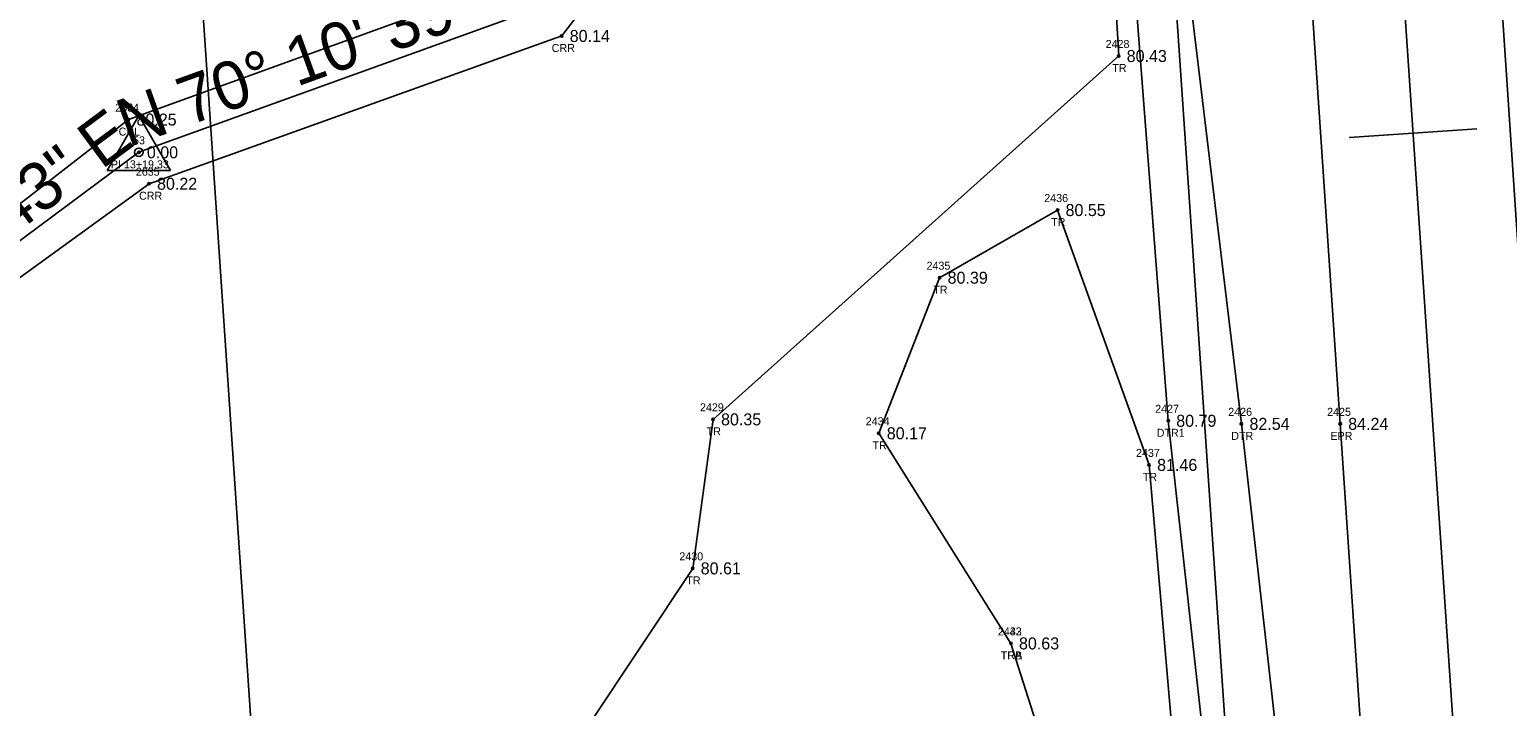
# Model space of a CAD drawing. Extents: x 2139392 to 2143384, y 505395 to 510520.
# Drawn here: x 2140461 to 2140645.6, y 506654.9 to 506739.4 of the extents above; entities that cross this region are included whole.
import ezdxf

# ---------------------------------------------------------------- set-up
doc = ezdxf.new("R2010")
doc.units = 0
for name, color, linetype in [('RD_EV_EX_Wetlands', 7, 'Continuous'), ('RD_EX_H2O', 7, 'Continuous'), ('RD_EX_H2O_txCode', 7, 'Continuous'), ('RD_EX_Road', 7, 'Continuous'), ('RD_EX_Road_txCode', 7, 'Continuous'), ('RD_EX_TX_H2O_ELEV', 7, 'Continuous'), ('RD_EX_TX_Road_ELEV', 7, 'Continuous'), ('RD_EX_TX_VEG_ELEV', 7, 'Continuous'), ('RD_EX_VEG', 7, 'Continuous'), ('RD_EX_VEG_txCode', 7, 'Continuous'), ('RD_HC_Cl', 7, 'Continuous'), ('RD_HC_Data', 7, 'Continuous'), ('RD_HC_Data_Tic', 7, 'Continuous'), ('RD_HC_Survey_ELEV', 7, 'Continuous'), ('RD_HC_txCode', 7, 'Continuous'), ('RD_SMD_Locator', 7, 'Continuous')]:
    doc.layers.add(name, color=color, linetype=linetype)

msp = doc.modelspace()

# ---------------------------------------------------------------- linework, layer by layer
at = {"layer": 'RD_EV_EX_Wetlands'}
msp.add_line((2140635.69, 506280.8), (2140603.94, 506746.81), dxfattribs=at)
msp.add_lwpolyline([(2140635.69, 506280.8), (2140514.52, 506270.54), (2140464.28, 507012.49), (2140535.71, 507012.16)], dxfattribs=at)
at = {"layer": 'RD_EX_H2O'}
for points in [[(2140595.86, 506808.79), (2140590.86, 506807.57), (2140591.7, 506801.01), (2140576.01, 506792.99), (2140551.31, 506782.03), (2140521.97, 506745.85), (2140473.31, 506728.17), (2140432.02, 506696.18), (2140374.62, 506691.81), (2140362.76, 506675.27), (2140331.34, 506688.09), (2140289.89, 506693.34), (2140243.27, 506706.89), (2140157.85, 506698.32), (2140125.33, 506735.71)], [(2140599.39, 506797.89), (2140612.39, 506690.17), (2140624.13, 506585.64), (2140631.8, 506471.85), (2140639.71, 506372.71), (2140644.64, 506264.35)], [(2140597.11, 506796.14), (2140592.29, 506797.04), (2140578.11, 506789.28), (2140556.31, 506776.27), (2140527.45, 506738.61), (2140475.88, 506720.16), (2140433.27, 506689.29), (2140378.98, 506685.41), (2140363.61, 506658.12), (2140329.18, 506677.67), (2140287.66, 506681.81), (2140243.93, 506698.42), (2140156.17, 506695.49), (2140124.7, 506729.24)], [(2140592.29, 506797.04), (2140595.23, 506794.56), (2140603.24, 506690.55), (2140614.93, 506584.96), (2140623.5, 506470.62), (2140631.3, 506372.18), (2140637.44, 506263.69)]]:
    msp.add_lwpolyline(points, dxfattribs=at)
at = {"layer": 'RD_EX_Road'}
for points in [[(2140559.74, 507699.59), (2140559.81, 507681.93), (2140560.3, 507666.18), (2140562.28, 507610.8), (2140566.4, 507547.54), (2140570.03, 507492.8), (2140573.82, 507437.38), (2140577.82, 507379.04), (2140579.38, 507354.44), (2140581.03, 507330.09), (2140587.99, 507226.36), (2140590.86, 507184.68), (2140593.07, 507153.16), (2140595.23, 507123.79), (2140602.7, 507012.79), (2140610.01, 506906.42), (2140617.09, 506803.24), (2140624.73, 506690.17), (2140631.76, 506586.09), (2140639.51, 506472.79), (2140646.1, 506374.38), (2140653.64, 506264.11)], [(2140620.89, 507096.21), (2140626.38, 507013.96), (2140633.64, 506909.47), (2140640.76, 506804.87), (2140648.25, 506692.59), (2140655.54, 506588.36), (2140663.28, 506474.49), (2140669.92, 506375.75), (2140677.52, 506265.2)]]:
    msp.add_lwpolyline(points, dxfattribs=at)
at = {"layer": 'RD_EX_VEG'}
for points in [[(2140538.67, 507155.75), (2140561.07, 507147.8), (2140571.22, 507149.28), (2140587.08, 506901.77), (2140597.05, 506736.11), (2140546.36, 506690.73), (2140543.82, 506672.12), (2140517.74, 506632.93), (2140477.73, 506581.98)], [(2140583.59, 506662.75), (2140567.07, 506688.99), (2140574.67, 506708.42), (2140589.41, 506716.87), (2140600.85, 506685.04), (2140609.88, 506580.26), (2140583.59, 506662.75)]]:
    msp.add_lwpolyline(points, dxfattribs=at)
at = {"layer": 'RD_HC_Cl'}
for p, q in [((2140574.74, 507595.12), (2140664.08, 506281.81)), ((2140474.61, 506724.08), (2140525.23, 506742.33)), ((2140432.56, 506692.9), (2140474.61, 506724.08))]:
    msp.add_line(p, q, dxfattribs=at)
at = {"layer": 'RD_HC_Data'}
for p, q in [((2140470.64, 506721.79), (2140474.61, 506728.67)), ((2140474.61, 506728.67), (2140478.58, 506721.79)), ((2140470.64, 506721.79), (2140478.58, 506721.79))]:
    msp.add_line(p, q, dxfattribs=at)
msp.add_circle((2140474.61, 506724.08), 0.529, dxfattribs=at)
at = {"layer": 'RD_HC_Data_Tic'}
for q in [(2140641.81, 506727), (2140625.85, 506725.92)]:
    msp.add_line((2140633.83, 506726.46), q, dxfattribs=at)
at = {"layer": 'RD_SMD_Locator'}
for centre in [(2140527.45, 506738.61), (2140597.05, 506736.11), (2140473.31, 506728.17), (2140474.61, 506724.08), (2140475.88, 506720.16), (2140589.41, 506716.87), (2140574.67, 506708.42), (2140546.36, 506690.73), (2140603.24, 506690.55), (2140612.39, 506690.17), (2140624.73, 506690.17), (2140567.07, 506688.99), (2140600.85, 506685.04), (2140543.82, 506672.12), (2140583.59, 506662.75), (2140583.59, 506662.75)]:
    msp.add_circle(centre, 0.15, dxfattribs=at)

# ---------------------------------------------------------------- texts
at = {"layer": 'RD_EX_H2O_txCode'}
for s, p in [('CRR', (2140526.2, 506736.61)), ('2634', (2140471.66, 506729.17)), ('CRL', (2140472.08, 506726.17)), ('2635', (2140474.23, 506721.16)), ('CRR', (2140474.63, 506718.16)), ('2427', (2140601.61, 506691.55)), ('2426', (2140610.74, 506691.17)), ('DTR1', (2140601.8, 506688.55)), ('DTR', (2140611.12, 506688.17))]:
    msp.add_text(s, height=1, dxfattribs=at).set_placement(p)
at = {"layer": 'RD_EX_Road_txCode'}
for s, p in [('2425', (2140623.1, 506691.17)), ('EPR', (2140623.51, 506688.17))]:
    msp.add_text(s, height=1, dxfattribs=at).set_placement(p)
at = {"layer": 'RD_EX_TX_H2O_ELEV'}
for s, p in [('80.14', (2140528.45, 506737.86)), ('80.25', (2140474.31, 506727.42)), ('80.22', (2140476.88, 506719.41)), ('80.79', (2140604.24, 506689.8)), ('82.54', (2140613.39, 506689.42))]:
    msp.add_text(s, height=1.5, dxfattribs=at).set_placement(p)
at = {"layer": 'RD_EX_TX_Road_ELEV'}
msp.add_text('84.24', height=1.5, dxfattribs=at).set_placement((2140625.73, 506689.42))
at = {"layer": 'RD_EX_TX_VEG_ELEV'}
for s, p in [('80.43', (2140598.05, 506735.36)), ('80.55', (2140590.41, 506716.12)), ('80.39', (2140575.67, 506707.67)), ('80.35', (2140547.36, 506689.98)), ('80.17', (2140568.07, 506688.24)), ('81.46', (2140601.85, 506684.29)), ('80.61', (2140544.82, 506671.37)), ('80.63', (2140584.59, 506662)), ('80.63', (2140584.59, 506662))]:
    msp.add_text(s, height=1.5, dxfattribs=at).set_placement(p)
at = {"layer": 'RD_EX_VEG_txCode'}
for s, p in [('2428', (2140595.42, 506737.11)), ('TR', (2140596.25, 506734.11)), ('2436', (2140587.75, 506717.87)), ('TR', (2140588.61, 506714.87)), ('2435', (2140573.04, 506709.42)), ('TR', (2140573.88, 506706.42)), ('2429', (2140544.73, 506691.73)), ('2434', (2140565.44, 506689.99)), ('TR', (2140545.57, 506688.73)), ('TR', (2140566.28, 506686.99)), ('2437', (2140599.22, 506686.04)), ('TR', (2140600.06, 506683.04)), ('2430', (2140542.15, 506673.12)), ('TR', (2140543.03, 506670.12)), ('2433', (2140581.96, 506663.75)), ('2442', (2140581.96, 506663.75)), ('TRA', (2140582.31, 506660.75)), ('TRB', (2140582.32, 506660.75))]:
    msp.add_text(s, height=1, dxfattribs=at).set_placement(p)
at = {"layer": 'RD_HC_Data'}
for s, rotation, p in [('N 70%%d 10\' 39" E', 19.8225, (2140473.26, 506724.66)), ('N 53%%d 26\' 43" E', 36.5549, (2140430.51, 506692.63))]:
    msp.add_text(s, height=6, rotation=rotation, dxfattribs=at).set_placement(p)
at = {"layer": 'RD_HC_Survey_ELEV'}
msp.add_text('0.00', height=1.5, dxfattribs=at).set_placement((2140475.61, 506723.33))
at = {"layer": 'RD_HC_txCode'}
for s, p in [('53', (2140473.88, 506725.08)), ('PI 13+19.33', (2140471.11, 506722.08))]:
    msp.add_text(s, height=1, dxfattribs=at).set_placement(p)

doc.saveas('drawing.dxf')
